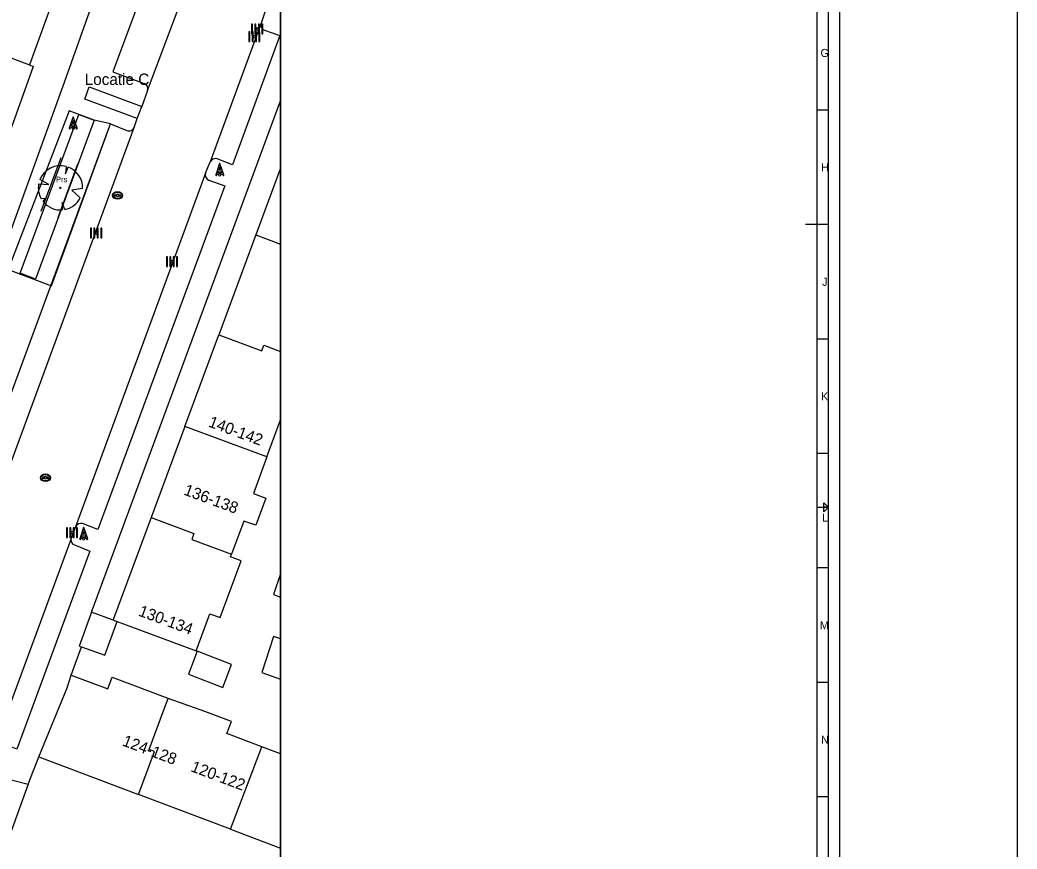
# Model space of a CAD drawing. Extents: x 192664 to 192925, y 446334 to 446521.
# Drawn here: x 192837.8 to 192925, y 446373.1 to 446445.5 of the extents above; entities that cross this region are included whole.
import ezdxf

# ---------------------------------------------------------------- set-up
doc = ezdxf.new("R2010")
doc.units = 0
for name, color, linetype in [('1010 viewport', 7, 'Continuous'), ('201011 legenda', 7, 'Continuous'), ('205134 wortelgeleidingsscherm', 7, 'Continuous'), ('B-GV-KG-GRENS_WERKGRENS-G', 7, 'Continuous'), ('bovenleidingmast', 7, 'Continuous'), ('huisnummerreeks BGT', 7, 'Continuous'), ('inspectie-   rioolput', 7, 'Continuous'), ('kant open verharding', 7, 'Continuous'), ('kant verharding', 7, 'Continuous'), ('kolk', 7, 'Continuous'), ('N-GV-GR-BOOM-S', 7, 'Continuous'), ('pand op maaiveld vlak', 7, 'Continuous'), ('TEKST', 7, 'Continuous'), ('verkeerseiland - berm', 7, 'Continuous'), ('X-XX-AL-TEKENBLAD-S', 7, 'Continuous'), ('X-XX-AL-TEKENBLAD_KADER-G', 7, 'Continuous')]:
    doc.layers.add(name, color=color, linetype=linetype)

msp = doc.modelspace()

# ---------------------------------------------------------------- linework, layer by layer
at = {"layer": '1010 viewport'}
msp.add_lwpolyline([(192675.743, 446509.756), (192860.643, 446509.756), (192860.643, 446345.556), (192675.743, 446345.556)], close=True, dxfattribs=at)
at = {"layer": '201011 legenda'}
msp.add_line((192860.643, 446345.556), (192860.643, 446509.756), dxfattribs=at)
at = {"layer": '205134 wortelgeleidingsscherm'}
for p, q in [((192839.712, 446428.827), (192841.461, 446433.511)), ((192841.184, 446428.282), (192842.919, 446432.971))]:
    msp.add_line(p, q, dxfattribs=at)
at = {"layer": 'B-GV-KG-GRENS_WERKGRENS-G'}
msp.add_lwpolyline([(192845.78, 446436.459), (192844.328, 446436.785), (192842.142, 446437.586), (192836.819, 446423.746), (192840.619, 446422.317)], close=True, dxfattribs=at)
at = {"layer": 'bovenleidingmast'}
for p, q in [((192842.495, 446437.072), (192842.154, 446436.099)), ((192842.854, 446436.099), (192842.513, 446437.072)), ((192855.309, 446432.989), (192854.968, 446432.016)), ((192855.668, 446432.016), (192855.327, 446432.989)), ((192843.412, 446401.176), (192843.071, 446400.203)), ((192843.771, 446400.203), (192843.43, 446401.176))]:
    msp.add_line(p, q, dxfattribs=at)
for points in [[(192842.248, 446436.066), (192842.277, 446436.149), (192842.417, 446436.149)], [(192842.513, 446436.769), (192842.591, 446436.549), (192842.417, 446436.549), (192842.495, 446436.769)], [(192842.591, 446436.149), (192842.731, 446436.149), (192842.76, 446436.066)], [(192855.327, 446432.686), (192855.405, 446432.466), (192855.231, 446432.466), (192855.309, 446432.686)], [(192855.062, 446431.983), (192855.091, 446432.066), (192855.231, 446432.066)], [(192855.405, 446432.066), (192855.545, 446432.066), (192855.574, 446431.983)], [(192843.43, 446400.873), (192843.508, 446400.653), (192843.334, 446400.653), (192843.412, 446400.873)], [(192843.165, 446400.17), (192843.194, 446400.253), (192843.334, 446400.253)], [(192843.508, 446400.253), (192843.648, 446400.253), (192843.677, 446400.17)]]:
    msp.add_lwpolyline(points, dxfattribs=at)
for points in [[(192842.626, 446436.449), (192842.696, 446436.249), (192842.312, 446436.249), (192842.382, 446436.449)], [(192855.44, 446432.366), (192855.51, 446432.166), (192855.126, 446432.166), (192855.196, 446432.366)], [(192843.543, 446400.553), (192843.613, 446400.353), (192843.229, 446400.353), (192843.299, 446400.553)]]:
    msp.add_lwpolyline(points, close=True, dxfattribs=at)
for centre, radius, start, end in [((192842.504, 446437.069), 0.01, 19.29005, 160.70995), ((192842.201, 446436.082), 0.05, 160.70995, 340.70995), ((192842.504, 446436.099), 0.1, 0, 180), ((192842.504, 446436.099), 0.1, 180, 0), ((192842.504, 446436.099), 0.1, 30, 150), ((192842.504, 446436.766), 0.01, 19.29005, 160.70995), ((192842.807, 446436.082), 0.05, 199.29005, 19.29005), ((192855.318, 446432.986), 0.01, 19.29005, 160.70995), ((192855.318, 446432.683), 0.01, 19.29005, 160.70995), ((192855.015, 446431.999), 0.05, 160.70995, 340.70995), ((192855.318, 446432.016), 0.1, 0, 180), ((192855.318, 446432.016), 0.1, 180, 0), ((192855.318, 446432.016), 0.1, 30, 150), ((192855.621, 446431.999), 0.05, 199.29005, 19.29005), ((192843.421, 446401.173), 0.01, 19.29005, 160.70995), ((192843.421, 446400.87), 0.01, 19.29005, 160.70995), ((192843.118, 446400.186), 0.05, 160.70995, 340.70995), ((192843.421, 446400.203), 0.1, 0, 180), ((192843.421, 446400.203), 0.1, 180, 0), ((192843.421, 446400.203), 0.1, 30, 150), ((192843.724, 446400.186), 0.05, 199.29005, 19.29005)]:
    msp.add_arc(centre, radius, start, end, dxfattribs=at)
at = {"layer": 'inspectie-   rioolput'}
for p, q in [((192846.289, 446430.243), (192846.132, 446430.243)), ((192846.132, 446430.169), (192846.289, 446430.169)), ((192846.632, 446430.243), (192846.475, 446430.243)), ((192846.475, 446430.169), (192846.632, 446430.169)), ((192839.984, 446405.579), (192839.827, 446405.579)), ((192840.327, 446405.579), (192840.17, 446405.579)), ((192839.827, 446405.504), (192839.984, 446405.504)), ((192840.17, 446405.504), (192840.327, 446405.504))]:
    msp.add_line(p, q, dxfattribs=at)
for centre, radius, start, end in [((192846.132, 446430.206), 0.0375, 90, 270), ((192846.382, 446430.206), 0.1, 0, 180), ((192846.382, 446430.206), 0.1, 157.97569, 180), ((192846.382, 446430.206), 0.1, 180, 202.02431), ((192846.382, 446430.206), 0.1, 180, 0), ((192846.382, 446430.206), 0.1, 0, 22.02431), ((192846.382, 446430.206), 0.1, 337.97569, 0), ((192846.632, 446430.206), 0.0375, 270, 90), ((192839.827, 446405.542), 0.0375, 90, 270), ((192840.077, 446405.542), 0.1, 0, 180), ((192840.077, 446405.542), 0.1, 157.97569, 180), ((192840.077, 446405.542), 0.1, 0, 22.02431), ((192840.327, 446405.542), 0.0375, 270, 90), ((192840.077, 446405.542), 0.1, 180, 202.02431), ((192840.077, 446405.542), 0.1, 180, 0), ((192840.077, 446405.542), 0.1, 337.97569, 0)]:
    msp.add_arc(centre, radius, start, end, dxfattribs=at)
for centre, major_axis, ratio in [((192846.382, 446430.206), (-0.442, 0), 0.73911), ((192846.382, 446430.206), (-0.392, 0), 0.689655), ((192840.077, 446405.542), (-0.442, 0), 0.73911), ((192840.077, 446405.542), (-0.392, 0), 0.689655)]:
    msp.add_ellipse(centre, major_axis=major_axis, ratio=ratio, dxfattribs=at)
at = {"layer": 'kant open verharding'}
for p, q in [((192859.639, 446447.374), (192858.944, 446445.253)), ((192844.09, 446393.794), (192860.643, 446438.476)), ((192847.824, 446436.149), (192848.102, 446436.917)), ((192842.706, 446401.261), (192842.311, 446400.15)), ((192842.324, 446388.292), (192843.225, 446390.76)), ((192838.566, 446378.775), (192839.5, 446381.146)), ((192838.566, 446378.775), (192827.102, 446347.165)), ((192836.641, 446379.267), (192838.566, 446378.775))]:
    msp.add_line(p, q, dxfattribs=at)
for points in [[(192846.946, 446454.816), (192845.635, 446451.129), (192845.293, 446450.169), (192841.851, 446440.492), (192835.693, 446423.446), (192835.401, 446422.35)], [(192848.102, 446436.917), (192843.514, 446438.619), (192843.896, 446439.682), (192848.491, 446437.98)]]:
    msp.add_lwpolyline(points, dxfattribs=at)
at = {"layer": 'kant verharding'}
for p, q in [((192858.944, 446445.253), (192854.473, 446433.152)), ((192849.014, 446439.367), (192848.491, 446437.98)), ((192848.102, 446436.917), (192848.491, 446437.98)), ((192835.879, 446403.721), (192847.824, 446436.149)), ((192854.067, 446432.141), (192854.473, 446433.152)), ((192854.067, 446432.141), (192842.706, 446401.261)), ((192842.311, 446400.15), (192835.688, 446382.26))]:
    msp.add_line(p, q, dxfattribs=at)
for points in [[(192849.014, 446439.367), (192852.558, 446448.85), (192852.92, 446450.686), (192852.89, 446452.743), (192852.529, 446454.425), (192852.02, 446455.701), (192852.016, 446455.709)], [(192849.233, 446449.789), (192845.968, 446441.003), (192848.719, 446439.99)], [(192859.223, 446444.637), (192860.582, 446444.192), (192856.425, 446432.876), (192855.1, 446433.409)], [(192835.578, 446404.274), (192834.092, 446404.819), (192845.78, 446436.459), (192847.207, 446435.879)], [(192854.375, 446431.535), (192855.749, 446431.055), (192844.653, 446401.014), (192843.315, 446401.529)], [(192842.625, 446399.67), (192843.965, 446399.128), (192837.574, 446381.816), (192836.276, 446382.332)]]:
    msp.add_lwpolyline(points, dxfattribs=at)
for centre, radius, start, end in [((192859.403, 446445.09), 0.487, 160.39436, 248.33929), ((192848.538, 446439.523), 0.501, 341.82266, 68.85387), ((192847.381, 446436.321), 0.475, 248.50933, 338.75917), ((192854.956, 446432.868), 0.56, 75.06, 149.51631), ((192854.559, 446432.01), 0.509, 165.03876, 248.84523), ((192843.168, 446401.037), 0.513, 73.33798, 154.16731), ((192842.733, 446400.083), 0.427, 170.99551, 255.38723)]:
    msp.add_arc(centre, radius, start, end, dxfattribs=at)
at = {"layer": 'kolk'}
for points in [[(192858.185, 446444.741), (192858.185, 446445.166), (192858.1, 446445.166), (192858.1, 446444.741), (192858.1, 446444.316), (192858.185, 446444.316)], [(192858.483, 446444.741), (192858.483, 446445.166), (192858.398, 446445.166), (192858.398, 446444.741), (192858.398, 446444.316), (192858.483, 446444.316)], [(192858.78, 446444.741), (192858.78, 446445.166), (192858.695, 446445.166), (192858.695, 446444.741), (192858.695, 446444.316), (192858.78, 446444.316)], [(192859.078, 446444.741), (192859.078, 446445.166), (192858.993, 446445.166), (192858.993, 446444.741), (192858.993, 446444.316), (192859.078, 446444.316)], [(192857.94, 446444.076), (192857.94, 446444.501), (192857.855, 446444.501), (192857.855, 446444.076), (192857.855, 446443.651), (192857.94, 446443.651)], [(192858.238, 446444.076), (192858.238, 446444.501), (192858.153, 446444.501), (192858.153, 446444.076), (192858.153, 446443.651), (192858.238, 446443.651)], [(192858.535, 446444.076), (192858.535, 446444.501), (192858.45, 446444.501), (192858.45, 446444.076), (192858.45, 446443.651), (192858.535, 446443.651)], [(192858.833, 446444.076), (192858.833, 446444.501), (192858.748, 446444.501), (192858.748, 446444.076), (192858.748, 446443.651), (192858.833, 446443.651)], [(192844.104, 446426.912), (192844.104, 446427.337), (192844.019, 446427.337), (192844.019, 446426.912), (192844.019, 446426.487), (192844.104, 446426.487)], [(192844.402, 446426.912), (192844.402, 446427.337), (192844.317, 446427.337), (192844.317, 446426.912), (192844.317, 446426.487), (192844.402, 446426.487)], [(192844.699, 446426.912), (192844.699, 446427.337), (192844.614, 446427.337), (192844.614, 446426.912), (192844.614, 446426.487), (192844.699, 446426.487)], [(192844.997, 446426.912), (192844.997, 446427.337), (192844.912, 446427.337), (192844.912, 446426.912), (192844.912, 446426.487), (192844.997, 446426.487)], [(192850.738, 446424.412), (192850.738, 446424.837), (192850.653, 446424.837), (192850.653, 446424.412), (192850.653, 446423.987), (192850.738, 446423.987)], [(192851.036, 446424.412), (192851.036, 446424.837), (192850.951, 446424.837), (192850.951, 446424.412), (192850.951, 446423.987), (192851.036, 446423.987)], [(192851.333, 446424.412), (192851.333, 446424.837), (192851.248, 446424.837), (192851.248, 446424.412), (192851.248, 446423.987), (192851.333, 446423.987)], [(192851.631, 446424.412), (192851.631, 446424.837), (192851.546, 446424.837), (192851.546, 446424.412), (192851.546, 446423.987), (192851.631, 446423.987)], [(192841.992, 446400.749), (192841.992, 446401.174), (192841.907, 446401.174), (192841.907, 446400.749), (192841.907, 446400.324), (192841.992, 446400.324)], [(192842.29, 446400.749), (192842.29, 446401.174), (192842.205, 446401.174), (192842.205, 446400.749), (192842.205, 446400.324), (192842.29, 446400.324)], [(192842.587, 446400.749), (192842.587, 446401.174), (192842.502, 446401.174), (192842.502, 446400.749), (192842.502, 446400.324), (192842.587, 446400.324)], [(192842.885, 446400.749), (192842.885, 446401.174), (192842.8, 446401.174), (192842.8, 446400.749), (192842.8, 446400.324), (192842.885, 446400.324)]]:
    msp.add_lwpolyline(points, close=True, dxfattribs=at)
for centre, start, end in [((192858.589, 446444.741), 0, 180), ((192858.344, 446444.076), 0, 180), ((192858.344, 446444.076), 180, 0), ((192858.589, 446444.741), 180, 0), ((192844.508, 446426.912), 0, 180), ((192844.508, 446426.912), 180, 0), ((192851.142, 446424.412), 0, 180), ((192851.142, 446424.412), 180, 0), ((192842.396, 446400.749), 0, 180), ((192842.396, 446400.749), 180, 0)]:
    msp.add_arc(centre, 0.1, start, end, dxfattribs=at)
at = {"layer": 'N-GV-GR-BOOM-S'}
for points in [[(192841.885, 446432.742), (192841.828, 446432.103), (192842.056, 446432.688)], [(192839.485, 446431.214), (192840.379, 446431.172), (192839.591, 446431.586)], [(192843.326, 446430.82), (192842.376, 446430.658), (192843.119, 446429.997)], [(192839.891, 446429.644), (192840.044, 446429.94), (192839.704, 446429.918)], [(192841.772, 446428.971), (192841.552, 446429.589), (192841.529, 446428.938)]]:
    msp.add_lwpolyline(points, dxfattribs=at)
msp.add_circle((192841.39, 446430.87), 0.0577, dxfattribs=at)
for start, end in [(75.18441, 158.29895), (358.52408, 69.90661), (169.74905, 209.43023), (281.36007, 333.20465), (219.26669, 274.10684)]:
    msp.add_arc((192841.39, 446430.87), 1.936, start, end, dxfattribs=at)
at = {"layer": 'pand op maaiveld vlak'}
for p, q in [((192860.643, 446432.579), (192858.485, 446426.762)), ((192858.485, 446426.762), (192855.24, 446418.019)), ((192858.485, 446426.762), (192860.643, 446425.961)), ((192852.273, 446410.027), (192855.24, 446418.019)), ((192852.273, 446410.027), (192849.313, 446402.05)), ((192859.445, 446407.365), (192852.273, 446410.027)), ((192859.445, 446407.365), (192860.643, 446410.593)), ((192845.992, 446393.104), (192844.09, 446393.794)), ((192845.992, 446393.104), (192846.336, 446392.976)), ((192860.643, 446391.45), (192860.005, 446391.677)), ((192856.251, 446374.838), (192858.994, 446382.037)), ((192860.643, 446381.416), (192858.994, 446382.037)), ((192839.5, 446381.146), (192848.204, 446377.869)), ((192856.251, 446374.838), (192848.204, 446377.869)), ((192856.251, 446374.838), (192860.643, 446373.184))]:
    msp.add_line(p, q, dxfattribs=at)
for points in [[(192836.54, 446469.53), (192836.973, 446468.62), (192837.036, 446468.487), (192838.86, 446464.658), (192838.011, 446464.254), (192843.76, 446452.181), (192841.215, 446450.969), (192841.788, 446449.766), (192840.974, 446449.379), (192840.403, 446450.578), (192839.983, 446450.377), (192841.046, 446448.145), (192838.693, 446441.612)], [(192829.348, 446445.115), (192832.102, 446444.08), (192838.693, 446441.612)], [(192838.693, 446441.612), (192839.008, 446441.484), (192836.921, 446435.689)], [(192855.24, 446418.019), (192858.99, 446416.627), (192859.169, 446417.11), (192860.643, 446416.562)], [(192859.445, 446407.365), (192858.259, 446404.169), (192859.343, 446403.767), (192858.459, 446401.384), (192857.432, 446401.756), (192856.359, 446398.863)], [(192849.313, 446402.05), (192846.032, 446393.211), (192845.992, 446393.104)], [(192849.313, 446402.05), (192853.063, 446400.658), (192852.876, 446400.155), (192856.359, 446398.863)], [(192846.336, 446392.976), (192853.244, 446390.412), (192854.45, 446393.66), (192855.345, 446393.328), (192857.182, 446398.278), (192856.268, 446398.618), (192856.359, 446398.863)], [(192860.643, 446397.15), (192860.015, 446395.329), (192860.643, 446395.104)], [(192844.09, 446393.794), (192843.017, 446390.835), (192843.225, 446390.76)], [(192843.225, 446390.76), (192845.264, 446390.021), (192846.336, 446392.976)], [(192860.005, 446391.677), (192859.009, 446388.515), (192860.643, 446387.944)], [(192855.585, 446387.216), (192856.335, 446389.224), (192853.336, 446390.377), (192852.589, 446388.364), (192855.585, 446387.216)], [(192839.5, 446381.146), (192841.977, 446387.192), (192842.324, 446388.292)], [(192842.324, 446388.292), (192845.528, 446387.086), (192845.911, 446388.102), (192850.786, 446386.266), (192850.812, 446386.257)], [(192848.204, 446377.869), (192849.612, 446381.625), (192849.144, 446381.801), (192850.438, 446385.257), (192850.812, 446386.257)], [(192858.994, 446382.037), (192855.947, 446383.185), (192856.346, 446384.245), (192854.014, 446385.124), (192850.812, 446386.257)]]:
    msp.add_lwpolyline(points, dxfattribs=at)
at = {"layer": 'verkeerseiland - berm'}
msp.add_lwpolyline([(192844.328, 446436.785), (192839.219, 446422.899), (192837.863, 446423.41), (192842.999, 446437.265), (192844.328, 446436.785)], dxfattribs=at)
at = {"layer": 'X-XX-AL-TEKENBLAD-S'}
for p, q in [((192909.543, 446343.556), (192909.543, 446511.756)), ((192908.543, 446344.556), (192908.543, 446510.756)), ((192908.543, 446437.656), (192907.543, 446437.656)), ((192908.543, 446417.656), (192907.543, 446417.656)), ((192908.543, 446407.656), (192907.543, 446407.656)), ((192907.543, 446402.956), (192908.543, 446402.956)), ((192908.143, 446402.956), (192908.543, 446402.956)), ((192908.543, 446402.956), (192908.143, 446402.956)), ((192908.543, 446397.656), (192907.543, 446397.656)), ((192908.543, 446387.656), (192907.543, 446387.656)), ((192908.543, 446377.656), (192907.543, 446377.656))]:
    msp.add_line(p, q, dxfattribs=at)
msp.add_lwpolyline([(192675.743, 446345.556), (192907.543, 446345.556), (192907.543, 446509.756), (192675.743, 446509.756)], close=True, dxfattribs=at)
for points in [[(192908.543, 446427.656), (192906.543, 446427.656)], [(192908.143, 446402.956), (192908.143, 446403.356), (192908.543, 446402.956)], [(192908.543, 446402.956), (192908.143, 446402.556), (192908.143, 446402.956)]]:
    msp.add_lwpolyline(points, dxfattribs=at)
at = {"layer": 'X-XX-AL-TEKENBLAD_KADER-G'}
msp.add_lwpolyline([(192664.22, 446520.974), (192925.029, 446520.974), (192925.029, 446333.894), (192664.22, 446333.894)], close=True, dxfattribs=at)

# ---------------------------------------------------------------- texts
at = {"layer": 'huisnummerreeks BGT'}
for s, rotation, p in [('140-142', 339.7, (192854.257, 446410.028)), ('136-138', 339.7, (192852.104, 446404.08)), ('130-134', 339.7, (192848.143, 446393.504)), ('124-128', 339.4, (192846.73, 446382.163)), ('120-122', 339.4, (192852.718, 446379.907))]:
    msp.add_text(s, height=1, rotation=rotation, dxfattribs=at).set_placement(p)
at = {"layer": 'TEKST'}
for s, height, p in [('Locatie C', 1, (192843.511, 446439.857)), ('Prs', 0.5, (192840.993, 446431.353))]:
    msp.add_text(s, height=height, dxfattribs=at).set_placement(p)
at = {"layer": 'X-XX-AL-TEKENBLAD-S'}
for s, p in [('G', (192907.843, 446442.306)), ('H', (192907.893, 446432.306)), ('J', (192907.993, 446422.306)), ('K', (192907.893, 446412.306)), ('L', (192907.993, 446401.706)), ('M', (192907.793, 446392.306)), ('N', (192907.893, 446382.306))]:
    msp.add_text(s, height=0.7, dxfattribs=at).set_placement(p)

doc.saveas('drawing.dxf')
